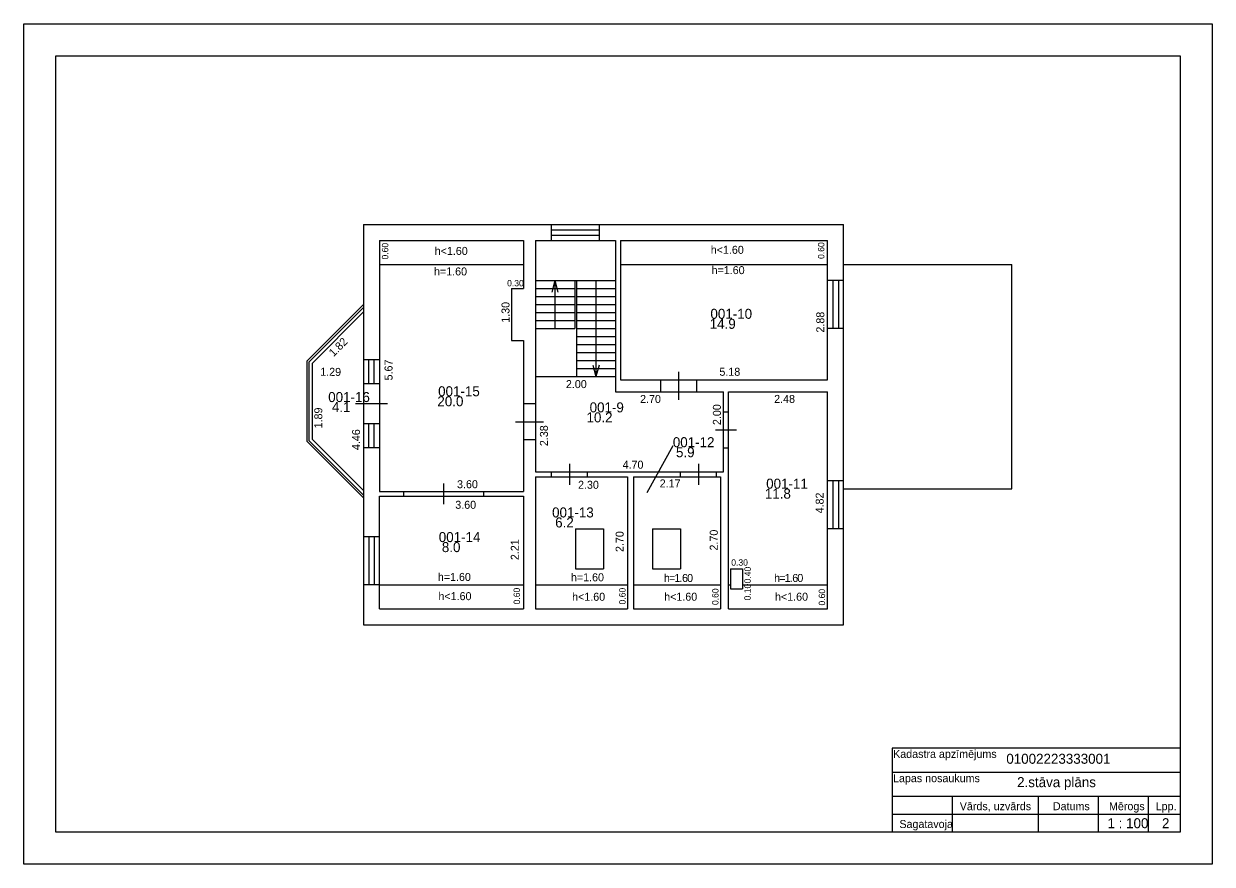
# Model space of a CAD drawing. Extents: x 509118.3 to 509148, y 311125.9 to 311169.7.
# Drawn here: x 509118.26 to 509147.96, y 311125.88 to 311146.88 of the extents above; entities that cross this region are included whole.
import ezdxf

# ---------------------------------------------------------------- set-up
doc = ezdxf.new("R2010")
doc.units = 0
for name, color, linetype in [('BUVE_EKAS_RKTL_FORM_#', 7, 'Continuous'), ('BUVE_EKAS_STPL_ASIE_#', 7, 'Continuous'), ('BUVE_EKAS_STPL_H1k6_#', 7, 'Continuous'), ('BUVE_EKAS_STPL_PLOG_#', 7, 'Continuous'), ('BUVE_EKAS_STPL_RAM#_#', 7, 'Continuous'), ('BUVE_EKAS_STPL_SIEN_#', 7, 'Continuous'), ('BUVE_EKAS_STPL_TKST_#', 7, 'Continuous'), ('BUVE_TELP_STPL_ELEM_#', 7, 'Continuous'), ('BUVE_TELP_STPL_IZMR_#', 7, 'Continuous'), ('BUVE_TELP_STPL_PLAT_#', 7, 'Continuous'), ('BUVE_TELP_STPL_TLNR_#', 7, 'Continuous')]:
    doc.layers.add(name, color=color, linetype=linetype)

# ---------------------------------------------------------------- blocks, each defined once
blk = doc.blocks.new('edurvis_1')
at = {"layer": 'BUVE_TELP_STPL_ELEM_#'}
for p, q in [((0.5, -1.667), (0.5, 2.667)), ((0, 0), (0, 1)), ((1, 0), (1, 1))]:
    blk.add_line(p, q, dxfattribs=at)
blk = doc.blocks.new('edurvis_2')
at = {"layer": 'BUVE_TELP_STPL_ELEM_#'}
for p, q in [((0.5, 2.667), (0.5, -1.667)), ((0, 0), (0, 1)), ((1, 0), (1, 1))]:
    blk.add_line(p, q, dxfattribs=at)
blk = doc.blocks.new('edurvis_3')
at = {"layer": 'BUVE_TELP_STPL_ELEM_#'}
for p, q in [((0.5, -0.667), (0.5, 1.667)), ((0, 0), (0, 1)), ((1, 0), (1, 1))]:
    blk.add_line(p, q, dxfattribs=at)
blk = doc.blocks.new('elogs')
at = {"layer": 'BUVE_TELP_STPL_ELEM_#'}
for p, q in [((0, 0), (0, 1)), ((1, 0), (1, 1)), ((1, 0.67), (0, 0.67)), ((1, 0.33), (0, 0.33))]:
    blk.add_line(p, q, dxfattribs=at)
blk = doc.blocks.new('bulta')
at = {"layer": 'BUVE_TELP_STPL_ELEM_#'}
for p in [(-0.29, 0.078), (-0.29, -0.078)]:
    blk.add_line(p, (0, 0), dxfattribs=at)
blk = doc.blocks.new('edurvis_4')
at = {"layer": 'BUVE_TELP_STPL_ELEM_#'}
for p, q in [((0.5, 1.667), (0.5, -0.667)), ((0, 0), (0, 1)), ((1, 0), (1, 1))]:
    blk.add_line(p, q, dxfattribs=at)
blk = doc.blocks.new('ramis')
at = {"layer": 'BUVE_EKAS_RKTL_FORM_#'}
blk.add_lwpolyline([(0, 0), (-1, 0), (-1, 1), (0, 1)], close=True, dxfattribs=at)
blk = doc.blocks.new('edurvis')
at = {"layer": 'BUVE_TELP_STPL_ELEM_#'}
for p, q in [((0.5, -0.5), (0.5, 1.5)), ((0, 0), (0, 1)), ((1, 0), (1, 1))]:
    blk.add_line(p, q, dxfattribs=at)

msp = doc.modelspace()

# ---------------------------------------------------------------- linework, layer by layer
at = {"layer": 'BUVE_EKAS_RKTL_FORM_#'}
for p, q in [((509139.959, 311128.779), (509139.959, 311126.679)), ((509147.159, 311128.779), (509139.959, 311128.779)), ((509147.159, 311128.779), (509147.159, 311126.679)), ((509139.959, 311128.179), (509139.959, 311126.679)), ((509139.959, 311128.179), (509147.159, 311128.179)), ((509139.959, 311127.579), (509147.159, 311127.579)), ((509141.459, 311127.579), (509141.459, 311126.679)), ((509143.609, 311127.579), (509143.609, 311126.679)), ((509145.109, 311127.579), (509145.109, 311126.679)), ((509146.359, 311127.579), (509146.359, 311126.679)), ((509139.959, 311127.129), (509147.159, 311127.129)), ((509147.159, 311126.679), (509139.959, 311126.679))]:
    msp.add_line(p, q, dxfattribs=at)
msp.add_lwpolyline([(509119.059, 311146.079), (509147.159, 311146.079), (509147.159, 311126.679), (509119.059, 311126.679)], close=True, dxfattribs=at)
at = {"layer": 'BUVE_EKAS_STPL_ASIE_#'}
for p, q in [((509126.748, 311141.862), (509138.748, 311141.862)), ((509126.748, 311141.862), (509126.748, 311131.862)), ((509138.748, 311131.862), (509138.748, 311141.862)), ((509138.748, 311140.862), (509142.948, 311140.862)), ((509142.948, 311135.262), (509142.948, 311140.862)), ((509138.748, 311135.262), (509142.948, 311135.262)), ((509126.748, 311131.862), (509138.748, 311131.862))]:
    msp.add_line(p, q, dxfattribs=at)
at = {"layer": 'BUVE_EKAS_STPL_H1k6_#'}
for p, q in [((509127.148, 311140.862), (509130.748, 311140.862)), ((509133.168, 311140.862), (509138.348, 311140.862)), ((509127.148, 311132.862), (509130.748, 311132.862)), ((509131.048, 311132.862), (509133.348, 311132.862)), ((509133.498, 311132.862), (509135.668, 311132.862)), ((509135.868, 311132.862), (509135.918, 311132.862)), ((509136.218, 311132.862), (509138.348, 311132.862))]:
    msp.add_line(p, q, dxfattribs=at)
at = {"layer": 'BUVE_EKAS_STPL_PLOG_#'}
for p, q in [((509132.048, 311134.262), (509132.748, 311134.262)), ((509132.048, 311134.262), (509132.048, 311133.262)), ((509132.748, 311134.262), (509132.748, 311133.262)), ((509133.968, 311134.262), (509133.968, 311133.262)), ((509133.968, 311134.262), (509134.668, 311134.262)), ((509134.668, 311134.262), (509134.668, 311133.262)), ((509132.048, 311133.262), (509132.748, 311133.262)), ((509133.968, 311133.262), (509134.668, 311133.262))]:
    msp.add_line(p, q, dxfattribs=at)
at = {"layer": 'BUVE_EKAS_STPL_SIEN_#'}
for p, q in [((509127.148, 311141.462), (509130.748, 311141.462)), ((509127.148, 311141.462), (509127.148, 311135.192)), ((509130.748, 311141.462), (509130.748, 311140.262)), ((509131.048, 311141.462), (509131.048, 311135.682)), ((509131.048, 311141.462), (509133.048, 311141.462)), ((509133.048, 311141.462), (509133.048, 311137.682)), ((509133.168, 311141.462), (509138.348, 311141.462)), ((509133.168, 311141.462), (509133.168, 311137.982)), ((509138.348, 311137.982), (509138.348, 311141.462)), ((509130.448, 311140.262), (509130.448, 311138.962)), ((509130.448, 311140.262), (509130.748, 311140.262)), ((509130.448, 311138.962), (509130.748, 311138.962)), ((509130.748, 311138.962), (509130.748, 311135.192)), ((509133.168, 311137.982), (509138.348, 311137.982)), ((509133.048, 311137.682), (509135.748, 311137.682)), ((509135.748, 311135.682), (509135.748, 311137.682)), ((509135.868, 311132.262), (509135.868, 311137.682)), ((509135.868, 311137.682), (509138.348, 311137.682)), ((509138.348, 311132.262), (509138.348, 311137.682)), ((509131.048, 311135.682), (509135.748, 311135.682)), ((509131.048, 311135.562), (509131.048, 311132.262)), ((509131.048, 311135.562), (509133.348, 311135.562)), ((509133.348, 311135.562), (509133.348, 311132.262)), ((509133.498, 311135.562), (509135.668, 311135.562)), ((509133.498, 311135.562), (509133.498, 311132.262)), ((509135.668, 311135.562), (509135.668, 311132.262)), ((509127.148, 311135.192), (509130.748, 311135.192)), ((509127.148, 311132.262), (509127.148, 311135.072)), ((509127.148, 311135.072), (509130.748, 311135.072)), ((509130.748, 311135.072), (509130.748, 311132.262)), ((509135.918, 311133.262), (509135.918, 311132.762)), ((509135.918, 311133.262), (509136.218, 311133.262)), ((509136.218, 311133.262), (509136.218, 311132.762)), ((509135.918, 311132.762), (509136.218, 311132.762)), ((509127.148, 311132.262), (509130.748, 311132.262)), ((509131.048, 311132.262), (509133.348, 311132.262)), ((509133.498, 311132.262), (509135.668, 311132.262)), ((509135.868, 311132.262), (509138.348, 311132.262))]:
    msp.add_line(p, q, dxfattribs=at)
at = {"layer": 'BUVE_TELP_STPL_ELEM_#'}
for p, q in [((509131.048, 311140.462), (509133.048, 311140.462)), ((509131.048, 311140.262), (509132.028, 311140.262)), ((509132.028, 311140.462), (509132.028, 311139.262)), ((509132.068, 311140.462), (509132.068, 311138.062)), ((509132.068, 311140.262), (509133.048, 311140.262)), ((509131.048, 311140.062), (509132.028, 311140.062)), ((509132.068, 311140.062), (509133.048, 311140.062)), ((509125.332, 311138.446), (509126.748, 311139.862)), ((509125.382, 311138.426), (509126.748, 311139.791)), ((509125.462, 311138.393), (509126.748, 311139.678)), ((509131.048, 311139.862), (509132.028, 311139.862)), ((509131.048, 311139.662), (509132.028, 311139.662)), ((509132.068, 311139.862), (509133.048, 311139.862)), ((509132.068, 311139.662), (509133.048, 311139.662)), ((509131.048, 311139.462), (509132.028, 311139.462)), ((509132.068, 311139.462), (509133.048, 311139.462)), ((509131.048, 311139.262), (509132.028, 311139.262)), ((509132.068, 311139.262), (509133.048, 311139.262)), ((509132.068, 311139.062), (509133.048, 311139.062)), ((509132.068, 311138.862), (509133.048, 311138.862)), ((509125.332, 311138.446), (509125.332, 311136.446)), ((509125.382, 311138.426), (509125.382, 311136.467)), ((509125.462, 311138.393), (509125.462, 311136.5)), ((509132.068, 311138.662), (509133.048, 311138.662)), ((509132.068, 311138.462), (509133.048, 311138.462)), ((509132.068, 311138.262), (509133.048, 311138.262)), ((509131.048, 311138.062), (509133.048, 311138.062)), ((509125.332, 311136.446), (509126.748, 311135.031)), ((509125.382, 311136.467), (509126.748, 311135.101)), ((509125.462, 311136.5), (509126.748, 311135.215))]:
    msp.add_line(p, q, dxfattribs=at)
for points in [[(509131.538, 311139.262), (509131.538, 311140.462)], [(509132.558, 311140.462), (509132.558, 311138.062)]]:
    msp.add_lwpolyline(points, dxfattribs=at)
at = {"layer": 'BUVE_TELP_STPL_TLNR_#'}
msp.add_line((509134.481, 311136.336), (509133.831, 311135.155), dxfattribs=at)

# ---------------------------------------------------------------- block references
at = {"layer": 'BUVE_EKAS_RKTL_FORM_#', "xscale": 29.6999999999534, "yscale": 20.9999999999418}
msp.add_blockref('ramis', (509147.959, 311125.879), dxfattribs=at)
at = {"layer": 'BUVE_TELP_STPL_ELEM_#'}
for name, p, xscale, yscale, rotation in [('elogs', (509132.648, 311141.462), 1.2, -0.4, 180), ('elogs', (509138.748, 311139.262), 1.2, 0.4, 90), ('elogs', (509126.748, 311138.492), 0.6, 0.4, -89.99999999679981), ('edurvis_3', (509135.068, 311137.982), 0.9, 0.3, 180), ('edurvis_4', (509131.048, 311136.482), 0.9, 0.3, 90), ('edurvis_1', (509135.748, 311137.182), 0.9, 0.12, -90.00000000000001), ('elogs', (509126.748, 311136.892), 0.6, 0.4, -89.99999999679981), ('edurvis_2', (509132.348, 311135.562), 0.9, -0.12, 180), ('edurvis_2', (509135.568, 311135.562), 0.9, -0.12, 180), ('elogs', (509138.748, 311134.262), 1.2, 0.4, 90), ('edurvis_1', (509129.748, 311135.192), 2, 0.12, 180), ('elogs', (509127.148, 311132.862), 1.2, 0.4, 90)]:
    msp.add_blockref(name, p, dxfattribs=dict(at, xscale=xscale, yscale=yscale, rotation=rotation))
for p, rotation in [((509131.538, 311140.462), 90), ((509132.558, 311138.062), -90.00000000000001)]:
    msp.add_blockref('bulta', p, dxfattribs=dict(at, rotation=rotation))
at = {"layer": 'BUVE_TELP_STPL_ELEM_#', "yscale": 0.4, "rotation": -90.00000000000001}
msp.add_blockref('edurvis', (509126.748, 311137.892), dxfattribs=at)

# ---------------------------------------------------------------- texts
at = {"layer": 'BUVE_EKAS_STPL_RAM#_#'}
for s, height, p in [('Kadastra apzīmējums', 0.2, (509139.985, 311128.535)), ('01002223333001', 0.25, (509142.813, 311128.389)), ('Lapas nosaukums', 0.2, (509139.982, 311127.929)), ('2.stāva plāns', 0.25, (509143.083, 311127.805)), ('Vārds, uzvārds', 0.2, (509141.65, 311127.229)), ('Datums', 0.2, (509143.977, 311127.229)), ('Mērogs', 0.2, (509145.379, 311127.229)), ('Lpp.', 0.2, (509146.546, 311127.229)), ('Sagatavoja', 0.2, (509140.141, 311126.784)), ('1 : 100', 0.25, (509145.342, 311126.779)), ('2', 0.25, (509146.703, 311126.779))]:
    msp.add_text(s, height=height, dxfattribs=at).set_placement(p)
at = {"layer": 'BUVE_EKAS_STPL_TKST_#'}
for s, p in [(' h<1.60', (509128.454, 311141.103)), (' h<1.60', (509135.353, 311141.131)), ('h=1.60', (509128.511, 311140.591)), ('h=1.60', (509135.448, 311140.624)), ('h=1.60', (509128.607, 311132.957)), ('h=1.60', (509131.933, 311132.948)), ('h', (509134.256, 311132.931)), ('=', (509134.384, 311132.931)), ('1', (509134.518, 311132.931)), ('6', (509134.709, 311132.931)), ('0', (509134.836, 311132.931)), ('h', (509137.011, 311132.932)), ('=', (509137.139, 311132.932)), ('1', (509137.273, 311132.932)), ('6', (509137.464, 311132.932)), ('0', (509137.591, 311132.932)), ('.', (509134.645, 311132.931)), ('.', (509137.4, 311132.932)), (' h<1.60', (509128.548, 311132.477)), (' h<1.60', (509131.888, 311132.462)), (' h<1.60', (509134.189, 311132.463)), (' h<1.60', (509136.958, 311132.463))]:
    msp.add_text(s, height=0.2, dxfattribs=at).set_placement(p)
at = {"layer": 'BUVE_TELP_STPL_IZMR_#'}
for s, height, rotation, p in [('0.60', 0.16, 90, (509127.369, 311140.989)), ('0.60', 0.16, 90, (509138.267, 311141.003)), ('1.30', 0.2, 90, (509130.398, 311139.408)), ('2.88', 0.2, 90, (509138.264, 311139.163)), ('1.82', 0.2, 45, (509126.001, 311138.547)), ('5.67', 0.2, 90, (509127.475, 311137.968)), ('1.29', 0.2, 359.2727, (509125.667, 311138.086)), ('1.89', 0.2, 90, (509125.719, 311136.769)), ('2.00', 0.2, 90, (509135.68, 311136.852)), ('4.46', 0.2, 90, (509126.662, 311136.227)), ('2.38', 0.2, 90, (509131.358, 311136.326)), ('4.82', 0.2, 90, (509138.248, 311134.645)), ('2.21', 0.2, 90, (509130.63, 311133.478)), ('2.70', 0.2, 90, (509133.25, 311133.68)), ('2.70', 0.2, 90, (509135.602, 311133.718)), ('0.40', 0.16, 90, (509136.429, 311132.897)), ('0.60', 0.16, 90, (509130.659, 311132.371)), ('0.60', 0.16, 90, (509133.298, 311132.37)), ('0.60', 0.16, 90, (509135.621, 311132.355)), ('0.10', 0.16, 90, (509136.427, 311132.47)), ('0.60', 0.16, 90, (509138.285, 311132.343))]:
    msp.add_text(s, height=height, rotation=rotation, dxfattribs=at).set_placement(p)
for s, height, p in [('0.30', 0.16, (509130.338, 311140.318)), ('5.18', 0.2, (509135.643, 311138.084)), ('2.00', 0.2, (509131.807, 311137.776)), ('2.70', 0.2, (509133.661, 311137.404)), ('2.48', 0.2, (509137.012, 311137.405)), ('4.70', 0.2, (509133.224, 311135.762)), ('3.60', 0.2, (509129.087, 311135.274)), ('2.30', 0.2, (509132.111, 311135.26)), ('2.17', 0.2, (509134.151, 311135.294)), ('3.60', 0.2, (509129.043, 311134.76)), ('0.30', 0.16, (509135.939, 311133.338))]:
    msp.add_text(s, height=height, dxfattribs=at).set_placement(p)
at = {"layer": 'BUVE_TELP_STPL_PLAT_#'}
for s, p in [('14.9', (509135.401, 311139.257)), ('20.0', (509128.595, 311137.322)), ('4.1', (509125.959, 311137.177)), ('10.2', (509132.322, 311136.919)), ('5.9', (509134.558, 311136.049)), ('11.8', (509136.778, 311135.013)), ('6.2', (509131.539, 311134.294)), ('8.0', (509128.707, 311133.678))]:
    msp.add_text(s, height=0.25, dxfattribs=at).set_placement(p)
at = {"layer": 'BUVE_TELP_STPL_TLNR_#'}
for s, p in [('001-10', (509135.419, 311139.507)), ('001-15', (509128.614, 311137.572)), ('001-16', (509125.867, 311137.427)), ('001-9', (509132.4, 311137.169)), ('001-12', (509134.479, 311136.299)), ('001-11', (509136.812, 311135.263)), ('001-13', (509131.462, 311134.544)), ('001-14', (509128.63, 311133.928))]:
    msp.add_text(s, height=0.25, dxfattribs=at).set_placement(p)

doc.saveas('drawing.dxf')
